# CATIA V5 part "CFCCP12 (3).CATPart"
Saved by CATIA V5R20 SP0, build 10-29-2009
Part number: CFCCP12 (3)
Revision: TUTTO
Definition: NON CONOSCIUTO
Nomenclature: CFCCP12 (3)
Source: Unknown
Bounding box of the stored display mesh (mm): x -60 to 60, y -60 to 60, z -50 to 0
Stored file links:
  C:\Users\Utente\Desktop\IO LAVORO\3D X SITO CF\X 3D SITO CF 27-09-2020\CFCCP\CFCCP12\CFCCP12 (3).CATPart
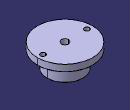
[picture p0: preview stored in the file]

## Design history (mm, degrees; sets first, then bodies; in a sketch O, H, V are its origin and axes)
Body1 "Foro Ø11.0 (11)-1" (main body)
  Solid1: solid without history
